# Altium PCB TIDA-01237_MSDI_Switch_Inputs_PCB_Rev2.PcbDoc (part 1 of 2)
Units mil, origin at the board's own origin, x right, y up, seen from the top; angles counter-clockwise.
Board outline 3000 x 5250 mil, 2 copper layers (Top Layer, Bottom Layer), stack 62 mil thick; 161 components, 119 nets, 511 pads, 360 vias.
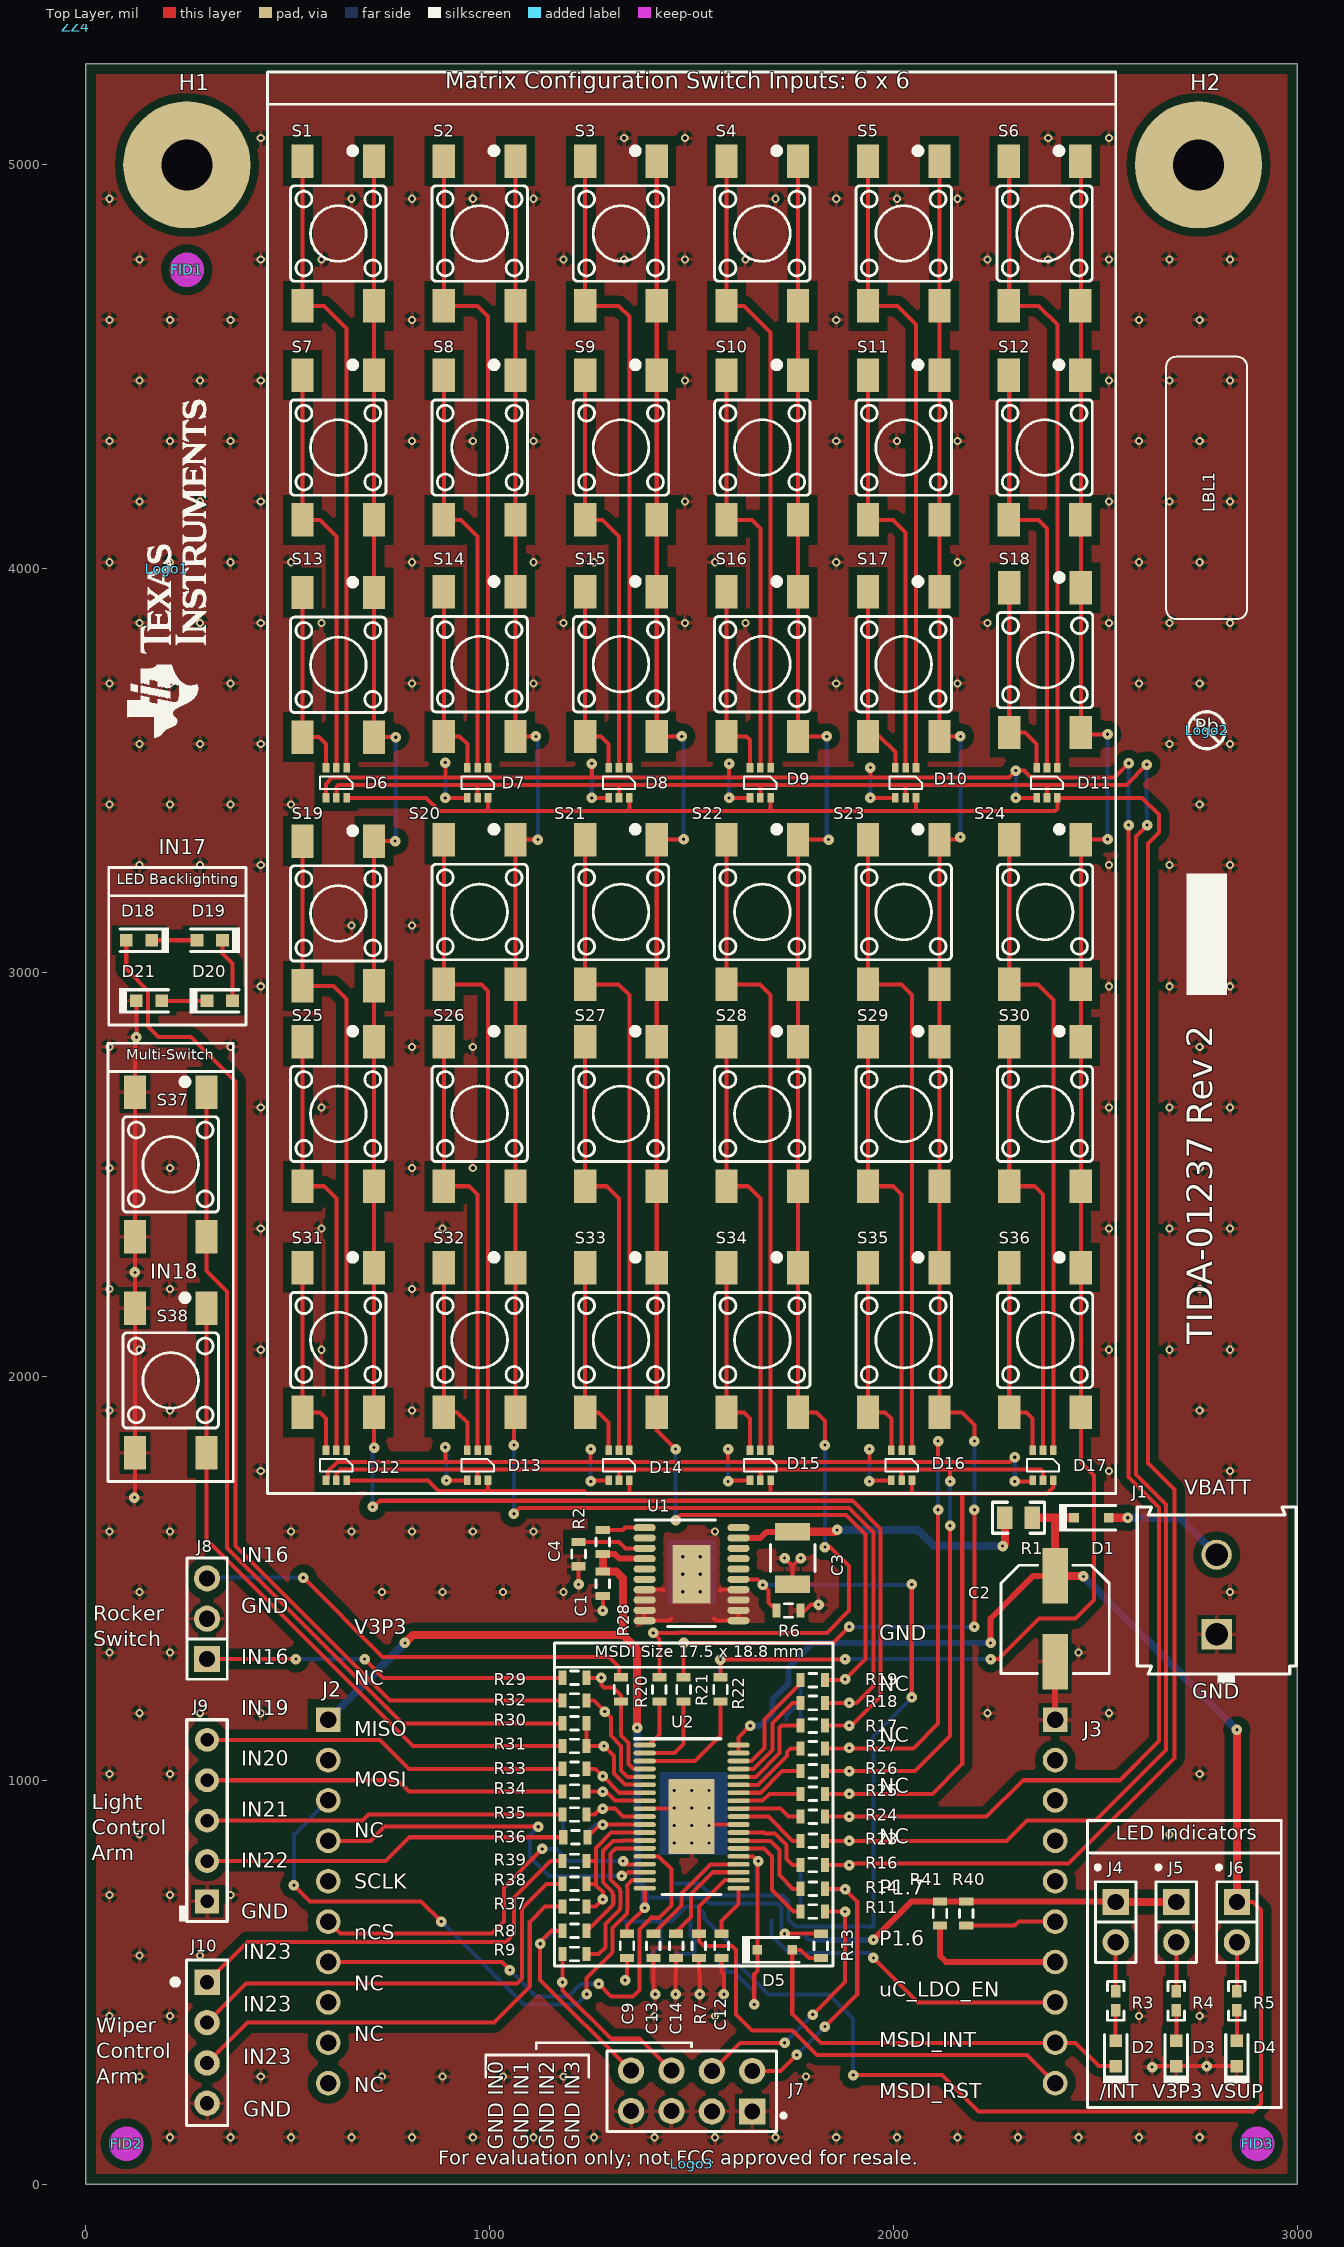
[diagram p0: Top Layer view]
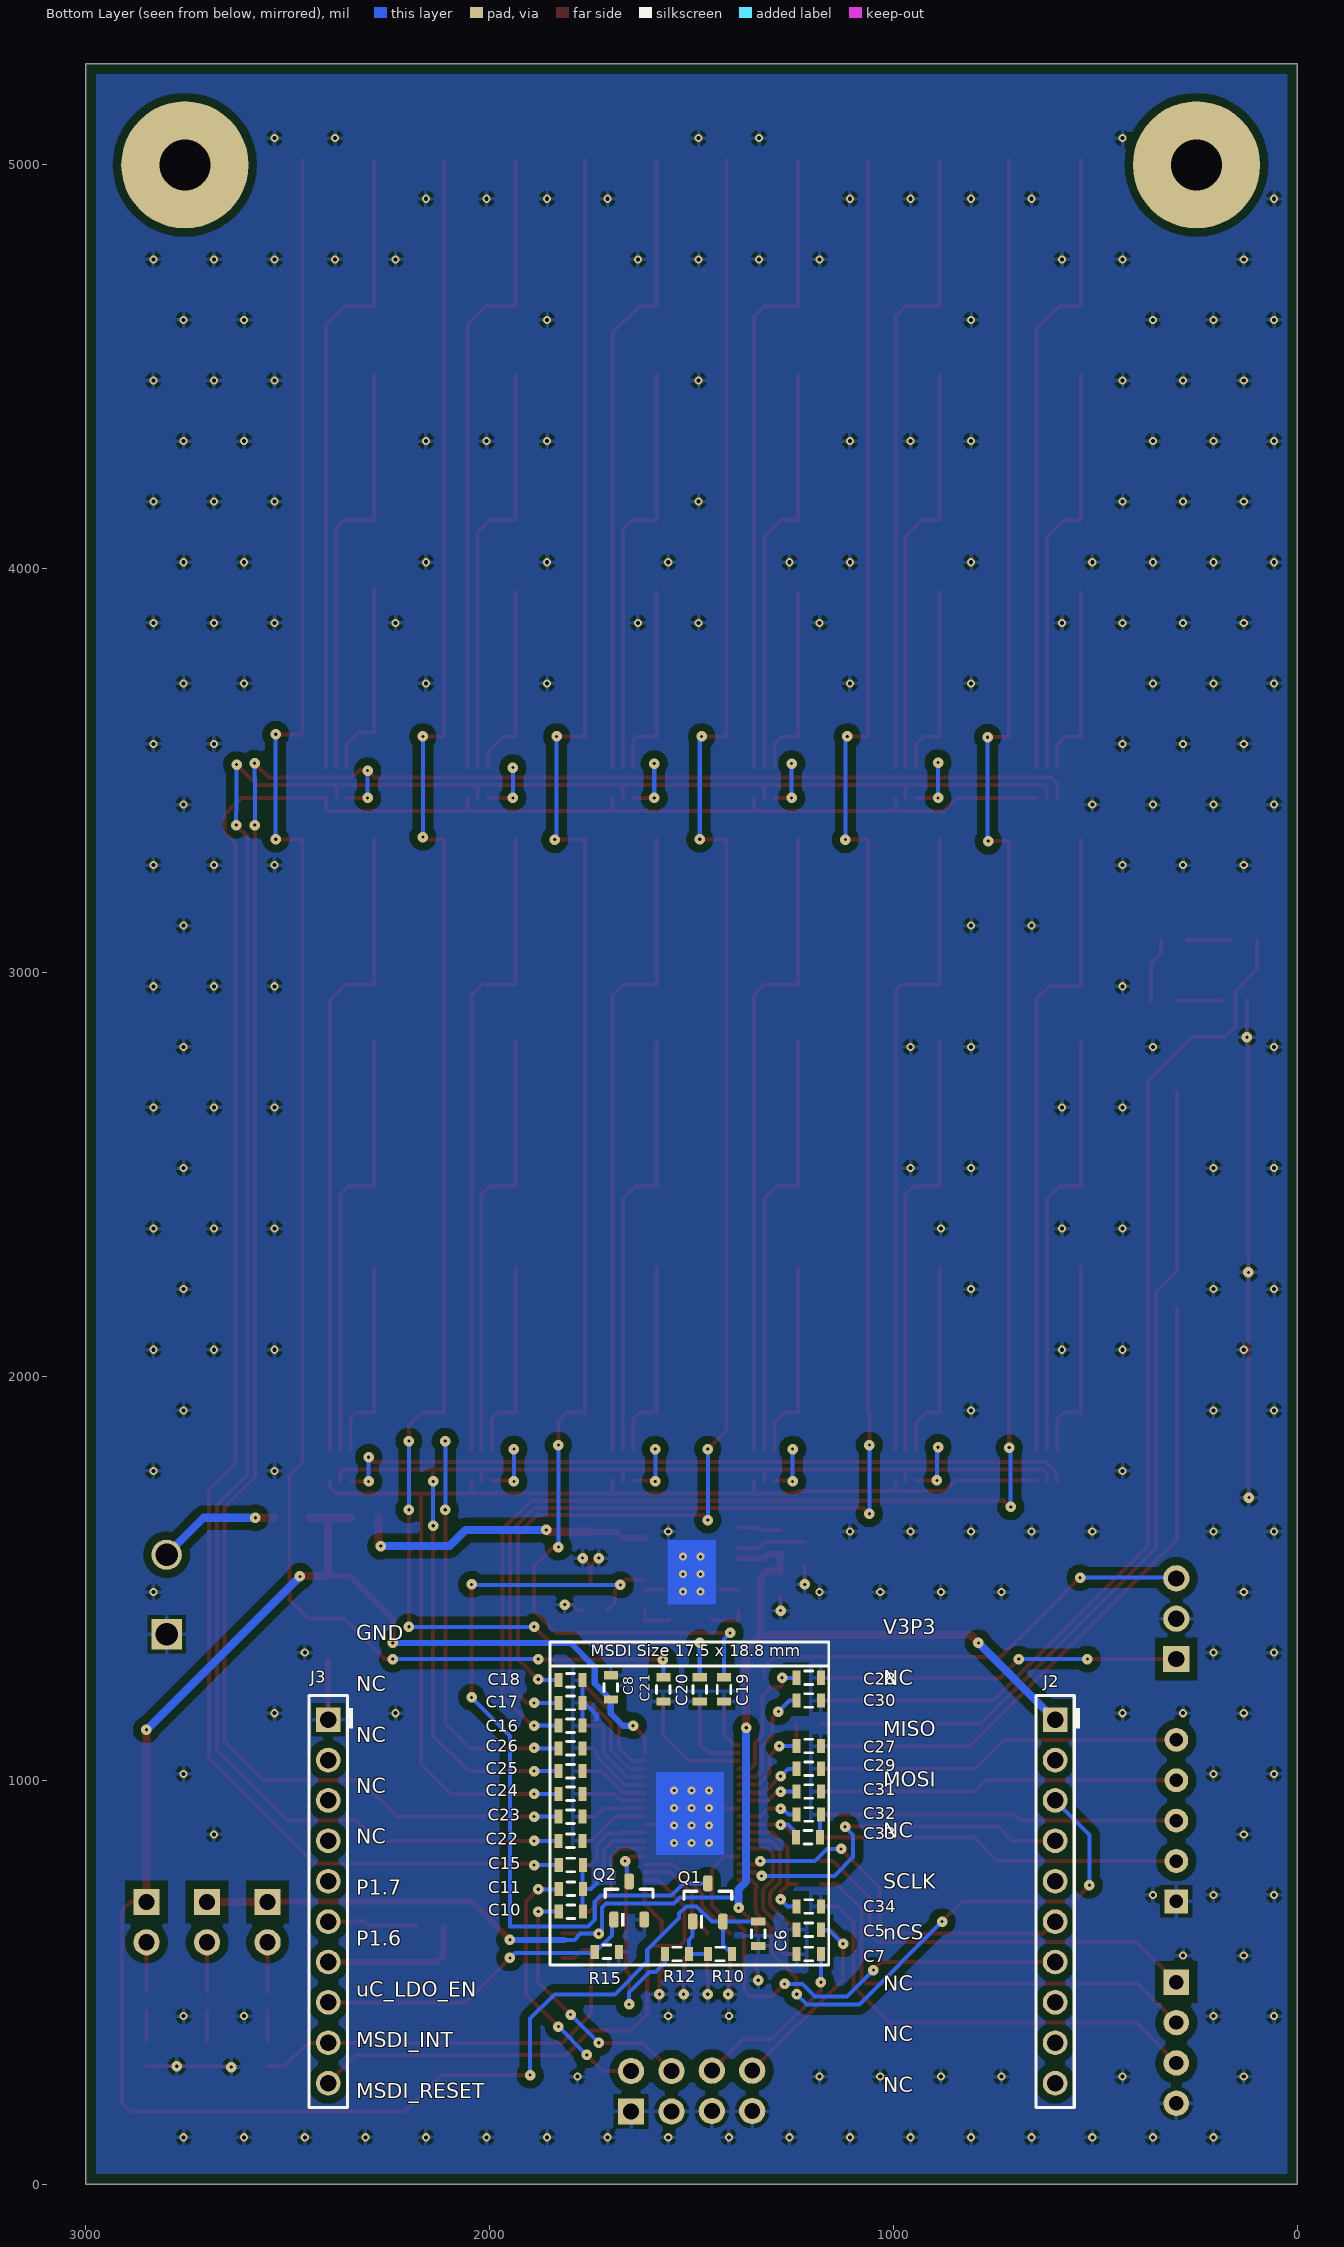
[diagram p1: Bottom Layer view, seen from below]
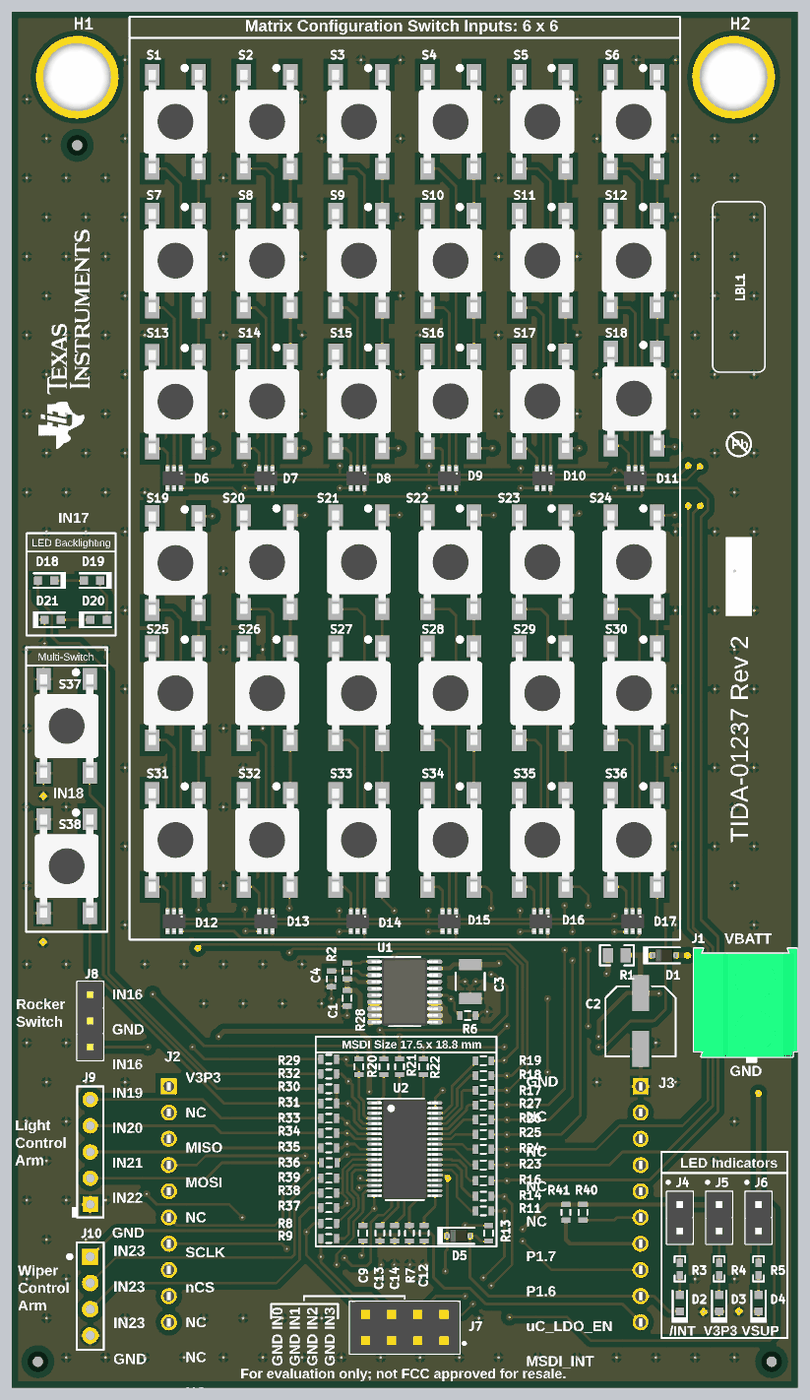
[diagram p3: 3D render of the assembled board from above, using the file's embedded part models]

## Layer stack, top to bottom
Top Solder: solder mask 0.4, Solder Resist, Dk 3.5
Top Layer: signal copper 1.4
Dielectric1: core 59.2, FR-4, Dk 4.8
Bottom Layer: signal copper 1.4
Bottom Solder: solder mask 0.4, Solder Resist, Dk 3.5

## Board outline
0,0 0,5250 3000,5250 3000,0

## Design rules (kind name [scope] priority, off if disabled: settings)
AcuteAngle [All] p1: minimum=4.50000000000000E+0001 checktracksonly=FALSE
AssemblyTestPointUsage [All] p1: valid=2
BoardOutlineClearance BoardOutlineClearance_MountingHoles [OnCopper and InComponentClass('Mounting Holes')] p1: gap=40
BoardOutlineClearance BoardOutlineClearance_Poly [OnCopper and IsPoly] p2: gap=25
BoardOutlineClearance [OnCopper and Not InComponentClass('Logo') and not InComponentClass('FiducialMark') and not InRegion(1000,500,4000,800) and not InPoly] p3: gap=75 except(45: Via-OutlineEdge)
Clearance Clearance_Keepouts [((IsTrack Or IsArc) And Not InPoly) And IsFree and IsKeepOut vs ((IsTrack Or IsArc) And Not InPoly) And IsFree and IsKeepOut] p1: gap=0
Clearance Clearance_Poly [InPolygon] p2: gap=20
Clearance [All] p3: gap=7.87
ComponentClearance ComponentClearance_MountingHoles_FiducialMarks [InComponentClass('Mounting Holes') vs InComponentClass('FiducialMark')] p1: gap=10 collisioncheckmode=3 verticalgap=10 showdistances=FALSE
ComponentClearance ComponentClearance_Shunt [InComponentClass('Header') vs InComponentClass('Shunt')] p2: gap=0 collisioncheckmode=3 verticalgap=0 showdistances=FALSE
ComponentClearance ComponentClearance_Logo [InComponentClass('Logo')] p3: gap=50 collisioncheckmode=3 verticalgap=10 showdistances=FALSE
ComponentClearance ComponentClearance_ScrewToNut [(HasFootprint('NY PMS 440 0025 PH')) vs (HasFootprint('Keystone_1902C'))] p4: gap=5 collisioncheckmode=3 verticalgap=10 showdistances=FALSE
ComponentClearance ComponentClearance_MountingHoles [InComponentClass('Mounting Holes')] p5: gap=100 collisioncheckmode=3 verticalgap=100000 showdistances=FALSE
ComponentClearance ComponentClearance_SmallPassives [HasFootprint('0201*') or HasFootprint('0402*') or HasFootprint('0508') or HasFootprint('0603*') or HasFootprint('0612') or HasFootprint('0805*') or HasFootprint('0815*') or HasFootprint('0830*') or HasFootprint('1206*') or HasFootprint('1210*') or HasFootprint('1808*') or HasFootprint('1812*') or HasFootprint('1825*') or HasFootprint('2010*') or HasFootprint('2220*') or HasFootprint('2225*') or HasFootprint('2512*') or HasFootprint('2728*') or HasFootprint('3518*') vs HasFootprint('0201*') or HasFootprint('0402*') or HasFootprint('0508') or HasFootprint('0603*') or HasFootprint('0612') or HasFootprint('0805*') or HasFootprint('0815*') or HasFootprint('0830*') or HasFootprint('1206*') or HasFootprint('1210*') or HasFootprint('1808*') or HasFootprint('1812*') or HasFootprint('1825*') or HasFootprint('2010*') or HasFootprint('2220*') or HasFootprint('2225*') or HasFootprint('2512*') or HasFootprint('2728*') or HasFootprint('3518*')] p6: gap=14.96 collisioncheckmode=3 verticalgap=10 showdistances=FALSE
ComponentClearance ComponentClearance_THtoSMT [IsThruComponent vs IsSMTComponent] p7: gap=40 collisioncheckmode=3 verticalgap=30 showdistances=FALSE
ComponentClearance ComponentClearance_THtoTH [IsThruComponent vs IsThruComponent] p8: gap=30 collisioncheckmode=3 verticalgap=30 showdistances=FALSE
ComponentClearance [All] p9: gap=30 collisioncheckmode=3 verticalgap=10 showdistances=FALSE
DiffPairsRouting [All] p1: maxlimit=100 minlimit=10 mostfreqgap=10 toplayer_minwidth=15 toplayer_maxwidth=15 toplayer_prefwidth=15 bottomlayer_minwidth=15 bottomlayer_maxwidth=15 bottomlayer_prefwidth=15 maxuncoupledlength=1000
FabricationTestPointUsage TestPointUsage [All] p1: valid=2 allowmultiple=FALSE
FabricationTestpoint Testpoint [All] p1: side=3 testpointundercomponent=TRUE minsize=40 maxsize=100 preferedsize=60 minholesize=0 maxholesize=40 preferedholesize=32 testpointgrid=1 allowsidetop=TRUE allowsidebottom=TRUE usegrid=TRUE gridtolerance=0.01
FanoutControl Fanout_LCC [IsLCC] p1: bgadir=Out bgaviamode=Centered fanoutstyle=Auto fanoutdirection=Alternating viagrid=1 // Fanout_LCC (Default Rule)
FanoutControl Fanout_BGA [IsBGA] p2: bgadir=Out bgaviamode=Centered fanoutstyle=Auto fanoutdirection=Alternating viagrid=1 // Fanout_BGA (Default Rule)
FanoutControl Fanout_Default [All] p4: bgadir=Out bgaviamode=Centered fanoutstyle=Auto fanoutdirection=Alternating viagrid=1 // Fanout_Default (Default Rule)
FanoutControl Fanout_Small [(CompPinCount < 5)] p5: bgadir=Out bgaviamode=Centered fanoutstyle=Auto fanoutdirection=OutThenIn viagrid=1 // Fanout_Small (Default Rule)
HoleSize [All] p1: absolutevalues=TRUE maxlimit=251 minlimit=7.87 maxpercent=80.000 minpercent=20.000
MinimumAnnularRing MinimumAnnularRing_ThermalPadVias [IsVia and InAnyComponent] p1: minimumring=5.91
MinimumAnnularRing [All] p2: minimumring=5
MinimumSolderMaskSliver MinimumSolderMaskSliver_Logo [InComponentClass('Logo') vs InComponentClass('Logo')] p1: minsoldermaskwidth=0.7
MinimumSolderMaskSliver [All] p2: minsoldermaskwidth=3.94
PlaneClearance [All] p1: clearance=15
PlaneConnect [All] p1: planeconnectstyle=Relief reliefexpansion=10 reliefentries=4 reliefconductorwidth=10 reliefairgap=10
PolygonConnect PolygonConnect_LDO [HasFootprint('PWP0020D_N')] p1: connectstyle=Direct reliefconductorwidth=10 reliefentries=4 polygonreliefangle="90 Angle" airgapwidth=10
PolygonConnect [All] p2: connectstyle=Relief reliefconductorwidth=10 reliefentries=4 polygonreliefangle="90 Angle" airgapwidth=10
RoutingVias ThermalPadVias [IsVia and InAnyComponent] p1: holewidth=7.87 width=19.68 viastyle="Through Hole" minholewidth=7.87 minwidth=19.68 maxholewidth=12.99 maxwidth=23.62
RoutingVias [All] p2: holewidth=7.87 width=26 viastyle="Through Hole" minholewidth=7.87 minwidth=20 maxholewidth=40 maxwidth=65
SilkToBoardRegionClearance [Not ((IsComment or IsDesignator) And (Hide <> 'False')) and not InRegion(1000,500,4000,800)] p1:
SilkToSilkClearance SilkToSilkClearance_Pb-FreeLogo [(HasFootprint('Pb-Free_Overlay_Medium') OR HasFootprint('Pb-Free_Overlay_Small')) vs (HasFootprint('Pb-Free_Overlay_Medium') OR HasFootprint('Pb-Free_Overlay_Small'))] p1: silktosilkclearance=0
SilkToSilkClearance [All] p2: silktosilkclearance=4
SilkToSolderMaskClearance SilkToComponentPadClearance [IsPad and InAnycomponent] p1: minsilkscreentomaskgap=5 clearancetoexposedcopper=TRUE
SilkToSolderMaskClearance "Silk to Solder Mask Opening" [All] p2: minsilkscreentomaskgap=4 clearancetoexposedcopper=FALSE
SolderMaskExpansion [All] p1: expansion=1.97
Width [All] p1: maxlimit=100 minlimit=6 preferedwidth=10 checkconnectedcopper=TRUE
14 further rules are at their usual default settings.

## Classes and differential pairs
component class "Mounting Holes": H1 H2
component class TIDA-01237_MSDI_Matrix_Inputs: C15 C16 C17 C18 C19 C20 C21 C22 C23 C24 C25 C26 D6 D7 D8 D9 D10 D11 D12 D13 D14 D15 D16 D17 R16 R17 R18 R19 R20 R21 R22 R23 R24 R25 R26 R27 S1 S2 S3 S4 S5 S6 S7 S8 S9 S10 S11 S12 S13 S14 S15 S16 S17 S18 S19 S20 S21 S22 S23 S24 S25 S26 S27 S28 S29 S30 S31 S32 S33 S34 S35 S36
component class Header: J4 J5 J6 J8 J9
component class Logo: Logo1
component class TIDA-01237_MSDI_Hardware: FID1 FID2 FID3 H1 H2 LBL1 Logo1 Logo2 Logo3 ZZ1 ZZ2 ZZ3 ZZ4
component class FiducialMark: FID1 FID2 FID3
component class AssemblyNote: ZZ1 ZZ2 ZZ3 ZZ4
component class Label: LBL1
component class TIDA-01237_MSDI_Main: C1 C2 C3 C4 C5 C6 C7 C8 C9 C10 C11 C12 C13 C14 D1 D2 D3 D4 D5 J1 J2 J3 J4 J5 J6 J7 Q1 Q2 R1 R2 R3 R4 R5 R6 R7 R8 R9 R10 R11 R12 R13 R14 R15 R40 R41 U1 U2
component class TIDA-01237_MSDI_Resistor_Coded_Inputs: C27 C28 C29 C30 C31 C32 C33 C34 D18 D19 D20 D21 J8 J9 J10 R28 R29 R30 R31 R32 R33 R34 R35 R36 R37 R38 R39 S37 S38

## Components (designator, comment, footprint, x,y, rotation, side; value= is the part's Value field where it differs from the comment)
C1 "C1608X5R1A106M080AC" 0603S 1280,1486.45 r270 top
C2 "EMVE500ADA470MF80G" CAPSMT_62_F80 2400,1400 r270 top
C3 "C3225X7R1H106M250AC" 1210_280 1750,1550.31 r270 top
C4 "C0603C103J5RACTU" 0603S 1220,1560 r270 top
C5 "C0603C153J3GACTU" 0603S 1210,629.69 r0 bottom
C6 "0603YC104JAT2A" 0603S 1335,620 r270 bottom
C7 "C0603C153J3GACTU" 0603S 1210,569.69 r0 bottom
C8 "06035C104KAT2A" 0603S 1700,1230 r90 bottom
C9 "0603YC104JAT2A" 0603S 1340,590 r270 top
C10 "C0603C153J3GACTU" 0603S 1799.18,674.68 r180 bottom
C11 "C0603C153J3GACTU" 0603S 1799.18,730.99 r180 bottom
C12 "C1608X7R1E104K080AA" 0603S 1574.1,590 r270 top
C13 "C1608X7R1E104K080AA" 0603S 1405.18,590 r270 top
C14 "C1608X7R1C105K080AC" 0603S 1461.48,590 r270 top
C15 "C0603C153J3GACTU" 0603S 1799.18,790 r180 bottom
C16 "C0603C153J3GACTU" 0603S 1800,1135.24 r180 bottom
C17 "C0603C153J3GACTU" 0603S 1800,1191.54 r180 bottom
C18 "C0603C153J3GACTU" 0603S 1800,1247.85 r180 bottom
C19 "C0603C153J3GACTU" 0603S 1420,1225 r270 bottom
C20 "C0603C153J3GACTU" 0603S 1480,1225 r270 bottom
C21 "C0603C153J3GACTU" 0603S 1570,1225 r270 bottom
C22 "C0603C153J3GACTU" 0603S 1800,850 r180 bottom
C23 "C0603C153J3GACTU" 0603S 1800,910 r180 bottom
C24 "C0603C153J3GACTU" 0603S 1800,966.31 r180 bottom
C25 "C0603C153J3GACTU" 0603S 1800,1022.62 r180 bottom
C26 "C0603C153J3GACTU" 0603S 1800,1078.93 r180 bottom
C27 "C0603C153J3GACTU" 0603S 1210,1084.76 r180 bottom
C28 "C0603C153J3GACTU" 0603S 1210,1253.69 r180 bottom
C29 "C0603C153J3GACTU" 0603S 1210,1028.45 r180 bottom
C30 "C0603C153J3GACTU" 0603S 1210,1197.38 r180 bottom
C31 "C0603C153J3GACTU" 0603S 1210,972.15 r180 bottom
C32 "C0603C153J3GACTU" 0603S 1210,915.24 r180 bottom
C33 "C0603C153J3GACTU" 0603S 1211.95,858.93 r180 bottom
C34 "C0603C153J3GACTU" 0603S 1210,687.38 r180 bottom
D1 "B0540WS-7" SOD-323 2490,1650 r0 top
D2 "150060VS75000" WL-SMCW_GREEN 2550,323.47 r90 top
D3 "150060VS75000" WL-SMCW_GREEN 2700,323.47 r90 top
D4 "150060VS75000" WL-SMCW_GREEN 2850,323.47 r90 top
D5 "SDMK0340L-7-F" SOD-323 1705.78,580 r0 top
D6 "BAS40TW-7-F" SOT-363 620,3470 r270 top
D7 "BAS40TW-7-F" SOT-363 970,3470 r270 top
D8 "BAS40TW-7-F" SOT-363 1320,3470 r270 top
D9 "BAS40TW-7-F" SOT-363 1670,3470 r270 top
D10 "BAS40TW-7-F" SOT-363 2030,3470 r270 top
D11 "BAS40TW-7-F" SOT-363 2380,3470 r270 top
D12 "BAS40TW-7-F" SOT-363 620,1780 r270 top
D13 "BAS40TW-7-F" SOT-363 970,1780 r270 top
D14 "BAS40TW-7-F" SOT-363 1320,1780 r270 top
D15 "BAS40TW-7-F" SOT-363 1670,1780 r270 top
D16 "BAS40TW-7-F" SOT-363 2020,1780 r270 top
D17 "BAS40TW-7-F" SOT-363 2370,1780 r270 top
D18 "150060VS75000" WL-SMCW_GREEN 131.54,3080 r180 top
D19 "150060VS75000" WL-SMCW_GREEN 306.54,3080 r180 top
D20 "150060VS75000" WL-SMCW_GREEN 331.54,2930 r0 top
D21 "150060VS75000" WL-SMCW_GREEN 156.54,2930 r0 top
FID1 "Fiducial" Fiducial10-20 250,4740 r0 top
FID2 "Fiducial" Fiducial10-20 100,100 r0 top
FID3 "Fiducial" Fiducial10-20 2900,100 r0 top
H1 "NY PMS 440 0025 PH" "NY PMS 440 0025 PH" 250,5000 r0 top
H2 "NY PMS 440 0025 PH" "NY PMS 440 0025 PH" 2755,5000 r0 top
J1 "282856-2" TE_282856-2 2800,1460 r90 top
J2 "SSW-110-01-T-S" Samtec_SSW-110-x1-x-S 600,700 r270 bottom
J3 "SSW-110-01-T-S" Samtec_SSW-110-x1-x-S 2400,700 r270 bottom
J4 "90120-0122" CONN_90120-0122 2550,648.81 r270 top
J5 "90120-0122" CONN_90120-0122 2700,648.81 r270 top
J6 "90120-0122" CONN_90120-0122 2850,648.81 r270 top
J7 "PPPC042LFBN-RC" CONN_PPPC042LFBN-RC 1650,180 r0 top
J8 "PBC03SAAN" PBC03SAAN 300,1400 r90 top
J9 "800-10-005-10-001000" Mill-Max_800-10-005-10-001000 300,900 r90 top
J10 "76308-204LF" FCI_76308-204LF 300,350 r90 top
LBL1 "Size: 0.65\" x 0.20 \"" Label_650x200 2775,4200 r90 top
Logo1 "Texas Instruments" TI_Stacked_Overlay_Small 200,4000 r90 top
Logo2 "Pb-Free Symbol" Pb-Free_Overlay_Small 2775,3600 r0 top
Logo3 "FCC disclaimer" FCC_disclaimer 1500,50 r0 top
Q1 "BC857C-7-F" SOT-23 1460,697.45 r90 bottom
Q2 "2N7002" SOT-23 1655,702.45 r90 bottom
R1 "5106" 5106 2310,1650 r180 top
R2 "CRCW060310K0JNEA" 0603S 1280,1590 r270 top
R3 "ERJ-2RKF49R9X" 0402 2550,453.8 r90 top
R4 "CRCW040268R0JNED" 0402 2700,453.8 r90 top
R5 "CRCW0402604RFKED" 0402 2850,453.8 r90 top
R6 "CRCW060310K0JNEA" 0603S 1740,1420.31 r180 top
R7 "CRCW060310K0JNEA" 0603S 1517.79,590 r90 top
R8 "CRCW0603100RFKEA" 0603S 1210,627.38 r0 top
R9 "CRCW0603100RFKEA" 0603S 1210,569.69 r0 top
R10 "CRCW060310K0JNEA" 0603S 1430,570 r180 bottom
R11 "CRCW0603100RFKEA" 0603S 1800,674.99 r180 top
R12 "CRCW060310K0JNEA" 0603S 1536.45,570 r0 bottom
R13 "CRCW060310K0JNEA" 0603S 1820,590 r90 top
R14 "CRCW0603100RFKEA" 0603S 1800,731.3 r180 top
R15 "CRCW060310K0JNEA" 0603S 1710,575 r180 bottom
R16 "CRCW0603100RFKEA" 0603S 1800,790 r180 top
R17 "CRCW0603100RFKEA" 0603S 1800,1135.24 r180 top
R18 "CRCW0603100RFKEA" 0603S 1800,1191.54 r180 top
R19 "CRCW0603100RFKEA" 0603S 1800,1247.85 r180 top
R20 "CRCW0603100RFKEA" 0603S 1420,1225 r270 top
R21 "CRCW0603100RFKEA" 0603S 1480,1225 r270 top
R22 "CRCW0603100RFKEA" 0603S 1571.23,1225 r270 top
R23 "CRCW0603100RFKEA" 0603S 1800,850 r180 top
R24 "CRCW0603100RFKEA" 0603S 1800,910 r180 top
R25 "CRCW0603100RFKEA" 0603S 1800,966.31 r180 top
R26 "CRCW0603100RFKEA" 0603S 1800,1022.62 r180 top
R27 "CRCW0603100RFKEA" 0603S 1800,1078.93 r180 top
R28 "CRCW0603909RFKEA" 0603S 1325,1225 r270 top
R29 "CRCW0603604RFKEA" 0603S 1210,1253.69 r0 top
R30 "CRCW0603392RFKEA" 0603S 1210,1141.07 r0 top
R31 "CRCW0603511RFKEA" 0603S 1210,1084.76 r0 top
R32 "CRCW060349R9FKEA" 0603S 1210,1197.38 r0 top
R33 "CRCW0603909RFKEA" 0603S 1210,1028.46 r0 top
R34 "CRCW0603604RFKEA" 0603S 1210,972.15 r0 top
R35 "CRCW0603309RFKEA" 0603S 1210,915.24 r0 top
R36 "CRCW06031K21FKEA" 0603S 1211.95,858.93 r0 top
R37 "CRCW06035K36FKEA" 0603S 1210,687.38 r0 top
R38 "CRCW06034K64FKEA" 0603S 1210,743.69 r0 top
R39 "CRCW06031K96FKEA" 0603S 1210,800 r0 top
R40 "RC0603JR-0710KL" 0603S 2180,670 r90 top
R41 "RC0603JR-0710KL" 0603S 2115,670 r90 top
S1 "4-1437565-1" SW_FSM4JSMA 625,4830 r0 top
S2 "4-1437565-1" SW_FSM4JSMA 975,4830 r0 top
S3 "4-1437565-1" SW_FSM4JSMA 1325,4830 r0 top
S4 "4-1437565-1" SW_FSM4JSMA 1675,4830 r0 top
S5 "4-1437565-1" SW_FSM4JSMA 2025,4830 r0 top
S6 "4-1437565-1" SW_FSM4JSMA 2373.93,4830 r0 top locked
S7 "4-1437565-1" SW_FSM4JSMA 625,4300 r0 top
S8 "4-1437565-1" SW_FSM4JSMA 975,4300 r0 top
S9 "4-1437565-1" SW_FSM4JSMA 1325,4300 r0 top
S10 "4-1437565-1" SW_FSM4JSMA 1675,4300 r0 top
S11 "4-1437565-1" SW_FSM4JSMA 2025,4300 r0 top
S12 "4-1437565-1" SW_FSM4JSMA 2373.93,4300 r0 top
S13 "4-1437565-1" SW_FSM4JSMA 625,3761.89 r0 top
S14 "4-1437565-1" SW_FSM4JSMA 975,3763.66 r0 top
S15 "4-1437565-1" SW_FSM4JSMA 1325,3763.66 r0 top
S16 "4-1437565-1" SW_FSM4JSMA 1675,3763.66 r0 top
S17 "4-1437565-1" SW_FSM4JSMA 2025,3763.66 r0 top
S18 "4-1437565-1" SW_FSM4JSMA 2375,3773.66 r0 top
S19 "4-1437565-1" SW_FSM4JSMA 625,3146.34 r0 top
S20 "4-1437565-1" SW_FSM4JSMA 975,3150 r0 top
S21 "4-1437565-1" SW_FSM4JSMA 1325,3150 r0 top
S22 "4-1437565-1" SW_FSM4JSMA 1675,3150 r0 top
S23 "4-1437565-1" SW_FSM4JSMA 2025,3150 r0 top
S24 "4-1437565-1" SW_FSM4JSMA 2375,3150 r0 top
S25 "4-1437565-1" SW_FSM4JSMA 625,2650 r0 top
S26 "4-1437565-1" SW_FSM4JSMA 975,2650 r0 top
S27 "4-1437565-1" SW_FSM4JSMA 1325,2650 r0 top
S28 "4-1437565-1" SW_FSM4JSMA 1675,2650 r0 top
S29 "4-1437565-1" SW_FSM4JSMA 2025,2650 r0 top
S30 "4-1437565-1" SW_FSM4JSMA 2375,2650 r0 top
S31 "4-1437565-1" SW_FSM4JSMA 625,2090 r0 top
S32 "4-1437565-1" SW_FSM4JSMA 975,2090 r0 top
S33 "4-1437565-1" SW_FSM4JSMA 1325,2090 r0 top
S34 "4-1437565-1" SW_FSM4JSMA 1675,2090 r0 top
S35 "4-1437565-1" SW_FSM4JSMA 2025,2090 r0 top
S36 "4-1437565-1" SW_FSM4JSMA 2375,2090 r0 top
S37 "4-1437565-1" SW_FSM4JSMA 210,2524.89 r0 top
S38 "4-1437565-1" SW_FSM4JSMA 210,1990 r0 top
U1 "TPS7B6733QPWPRQ1" PWP0020D_N 1499.68,1510.31 r0 top
U2 "TIC12400DCPQ1" DCP0038A_N 1500,910 r0 top
ZZ1 "This Assembly Note is for PCB labels only" AssemblyNoteLabel -25,5628 r0 top
ZZ2 "These assemblies are ESD sensitive, ESD precautions shall be observed." AssemblyNote -25,5519.11 r0 top
ZZ3 "These assemblies must be clean and free from flux and all contaminants. Use of no clean flux is not acceptable." AssemblyNote -25,5430.56 r0 top
ZZ4 "These assemblies must comply with workmanship standards IPC-A-610 Class 2, unless otherwise specified." AssemblyNote -25,5342 r0 top

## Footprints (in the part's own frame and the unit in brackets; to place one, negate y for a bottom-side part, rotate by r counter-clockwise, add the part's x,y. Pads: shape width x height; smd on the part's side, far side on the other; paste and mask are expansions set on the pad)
0402 [mm] "0402 from SM-752 data"
  rect 0.8x0.6 smd: 1(-0.6,0) 2(0.6,0)
  silkscreen extent -1.22,-0.52 1.22,0.52, body extent -0.55,-0.3 0.55,0.3, height 0.6
0603S [mil]
  rect 20x35 smd: 1(-30,0) 2(30,0)
  silkscreen extent -10,-17 10,17, body extent -34,-19 34,19, height 39
1210_280 [mm] "SMD, 2-Leads, Body 3.6x2.8mm, Height 2.8mm"
  rect 1.1x2.2 smd: 1(-1.65,0) 2(1.65,0)
  silkscreen extent -0.84,-1.4 0.84,1.4, body extent -1.8,-1.4 1.8,1.4, height 2.8
5106 [mm] "Keystone"
  rect 0.99x1.4 smd: 1(-0.85,0) 2(0.88,0)
  silkscreen extent -1.63,-0.97 1.65,0.97, body extent -1.06,-0.69 1.06,0.69, height 0.84
AssemblyNote [mil] "Assembly Note"
AssemblyNoteLabel [mil] "Assembly Note for PCB Labels"
CAPSMT_62_F80 [mm] "6.3 x 7.7mm:  Chemi-Con F80"
  rect 3.5x1.6 smd: 1(-2.7,0) 2(2.7,0)
  silkscreen extent -3.36,-3.4 3.44,3.4, body extent -3.4,-3.4 3.44,3.4, height 8
CONN_90120-0122 [mm] "Molex"
  rect 1.65x1.65 hole 1.016 mask+0: 1(-1.27,0)
  round 1.65 hole 1.016 mask+0: 2(1.27,0)
  silkscreen extent -3.56,-1.27 2.54,1.27, body extent -2.54,-1.27 2.54,1.27, height 9.29
CONN_PPPC042LFBN-RC [mm] "Sullins socket, 100 mil spacing, 4x2"
  rect 1.65x1.65 hole 1 mask+0: 1(0,0)
  round 1.65 hole 1 mask+0: 2(0,2.54) 3(-2.54,0) 4(-2.54,2.54) 5(-5.08,0.025) 6(-5.08,2.565) 7(-7.62,0.025) 8(-7.62,2.565)
  silkscreen extent -9.14,-1.27 2.09,3.81, body extent -9.14,-1.27 1.52,3.81, height 8.52
DCP0038A_N [mm] "SOP, 38-Leads, Body 9.8x4.5mm, Pitch 0.5mm, Thermal Pad 4.7x2.9mm, IPC Medium Density"
  oval 1.4x0.3 smd: 1(-2.95,4.5) 2(-2.95,4) 3(-2.95,3.5) 4(-2.95,3) 5(-2.95,2.5) 6(-2.95,2) 7(-2.95,1.5) 8(-2.95,1) 9(-2.95,0.5) 10(-2.95,0) 11(-2.95,-0.5) 12(-2.95,-1) 13(-2.95,-1.5) 14(-2.95,-2) 15(-2.95,-2.5) 16(-2.95,-3) 17(-2.95,-3.5) 18(-2.95,-4) 19(-2.95,-4.5) 20(2.95,-4.5) 21(2.95,-4) 22(2.95,-3.5) 23(2.95,-3) 24(2.95,-2.5) 25(2.95,-2) 26(2.95,-1.5) 27(2.95,-1) 28(2.95,-0.5) 29(2.95,0) 30(2.95,0.5) 31(2.95,1) 32(2.95,1.5) 33(2.95,2) 34(2.95,2.5) 35(2.95,3) 36(2.95,3.5) 37(2.95,4) 38(2.95,4.5)
  rrect3% 2.9x4.7 smd: 39(0,0)
  silkscreen extent -3.6,-4.9 1.85,4.9, body extent -3.21,-4.85 3.21,4.85, height 1.2
FCC_disclaimer [mil]
FCI_76308-204LF [mm] "FCI"
  rect 1.6x1.6 hole 0.9: 1(3.81,0)
  round 1.6 hole 0.9: 2(1.27,0) 3(-1.27,0) 4(-3.81,0)
  silkscreen extent -5.2,-1.3 5.2,2.18, body extent -5.19,-1.27 5.19,1.27, height 8.52
Fiducial10-20 [mm]
  round 1 smd mask+0.5: 1(0,0)
  Top Layer keep-out circle w1.178: c0,0 r0.5
Label_650x200 [mil] "Thermal Transfer Label"
  silkscreen extent -325,-100 325,100, body extent -325,-100 325,100, height 1
Mill-Max_800-10-005-10-001000 [mm] "Mill-Max"
  rect 1.5x1.5 hole 0.85: 1(-5.08,0)
  round 1.5 hole 0.85: 2(-2.54,0) 3(0,0) 4(2.54,0) 5(5.08,0)
  silkscreen extent -6.35,-1.27 6.35,1.78, body extent -6.35,-1.27 6.35,1.27, height 8.13
"NY PMS 440 0025 PH" [mm] "4-40 nylon screw and mounting hole"
  round 8 hole 3.2: 1(0,0)
  body extent -3.3,-3.3 3.3,3.3, height 2.69
Pb-Free_Overlay_Small [mil]
  silkscreen extent -46,-46 46,46
PBC03SAAN [mm] "Sullins 100mil, 1x3, 230 mil above insulator"
  rect 1.65x1.65 hole 1.016: 1(-2.54,0)
  round 1.65 hole 1.016: 2(0,0) 3(2.54,0)
  silkscreen extent -3.81,-1.27 3.81,1.27, body extent -3.81,-1.27 3.81,1.27, height 8.38
PWP0020D_N [mm] "SOP, 20-Leads, Body 6.4x4.4mm, Pitch 0.65mm, Thermal Pad 2x3mm, IPC Medium Density"
  rrect100% 1.4x0.45 smd: 1(-2.95,2.925) 2(-2.95,2.275) 3(-2.95,1.625) 4(-2.95,0.975) 5(-2.95,0.325) 6(-2.95,-0.325) 7(-2.95,-0.975) 8(-2.95,-1.625) 9(-2.95,-2.275) 10(-2.95,-2.925) 11(2.95,-2.925) 12(2.95,-2.275) 13(2.95,-1.625) 14(2.95,-0.975) 15(2.95,-0.325) 16(2.95,0.325) 17(2.95,0.975) 18(2.95,1.625) 19(2.95,2.275) 20(2.95,2.925)
  rrect4% 2.4x3.7 smd: 21(0,0)
  silkscreen extent -3.55,-3.3 1.5,3.4, body extent -3.21,-3.25 3.21,3.25, height 1
Samtec_SSW-110-x1-x-S [mm] "Receptacle, 2.54mm, 10x1, TH"
  rect 1.55x1.55 hole 1.04: 1(-11.43,0)
  round 1.55 hole 1.04: 2(-8.89,0) 3(-6.35,0) 4(-3.81,0) 5(-1.27,0) 6(1.27,0) 7(3.81,0) 8(6.35,0) 9(8.89,0) 10(11.43,0)
  silkscreen extent -12.95,-1.21 12.95,1.55, body extent -12.95,-1.21 12.95,1.21, height 8.51
SOD-323 [mm] "NXP recommended land pattern"
  rect 0.6x0.6 smd paste-0.05: 1(-1.1,0) 2(1.1,0)
  silkscreen extent -2.06,-0.86 1.53,0.86, body extent -1.3,-0.67 1.3,0.68, height 1.1
SOT-23 [mm] "SOT23, 3-Leads, Body 2.9x1.3mm, Pitch 0.95mm, Lead Span 2.5mm, IPC Medium Density"
  rrect50% 1x0.6 smd: 1(-1.2,0.95) 2(-1.2,-0.95) 3(1.2,0)
  silkscreen extent -1.62,-1.5 0.7,1.5, body extent -1.16,-1.45 1.21,1.45, height 1
SOT-363 [mm]
  rect 0.6x0.42 smd mask+0.051: 1(-0.95,0.65) 2(-0.95,0) 3(-0.95,-0.65) 4(0.95,-0.65) 5(0.95,0) 6(0.95,0.65)
  silkscreen extent -0.38,-1.02 0.38,1.02, body extent -1.1,-1.1 1.1,1.1, height 1.12
SW_FSM4JSMA [mm] "Alcoswitch"
  rect 1.4x2.1 smd: 1(2.25,4.55) 2(2.25,-4.55) 3(-2.25,4.55) 4(-2.25,-4.55)
  silkscreen extent -3,-3 3,5.4, body extent -3,-5 3,5, height 5.1
TE_282856-2 [mm] "TH, 2-Leads, Body 10x10mm, Pitch 5mm"
  rect 1.9x1.9 hole 1.4: 1(-2.5,0)
  round 1.9 hole 1.4: 2(2.5,0)
  silkscreen extent -5.61,-5 5.5,5, body extent -5,-5 5.5,5, height 19
TI_Stacked_Overlay_Small [mil]
  silkscreen extent -418,-98 418,98
WL-SMCW_GREEN [mm] "WURTH"
  rect 0.8x0.8 smd: 1(-0.8,0) 2(0.8,0)
  silkscreen extent -1.9,-0.8 1.2,0.8, body extent -0.85,-0.45 0.85,0.45, height 0.8

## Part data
C1: "CAP, CERM, 10 µF, 10 V, +/- 20%, X5R, 0603"
C2: "CAP, AL, 47 µF, 50 V, +/- 20%, SMD"
C3: "CAP, CERM, 10 µF, 50 V, +/- 20%, X7R, 1210"
C4: "CAP, CERM, 0.01 µF, 50 V, +/- 5%, X7R, 0603"
C5 C7 C10 C11 C15 C16 C17 C18 C19 C20 C21 C22 C23 C24 C25 C26 C27 C28 C29 C30 C31 C32 C33 C34: "CAP, CERM, 0.015 µF, 25 V, +/- 5%, C0G/NP0, 0603"
C6 C9: "CAP, CERM, 0.1 µF, 16 V, +/- 5%, X7R, 0603"
C8: "CAP, CERM, 0.1 µF, 50 V, +/- 10%, X7R, 0603"
C12 C13: "CAP, CERM, 0.1 µF, 25 V, +/- 10%, X7R, 0603"
C14: "CAP, CERM, 1 µF, 16 V, +/- 10%, X7R, 0603"
D1: "Diode, Schottky, 40 V, 0.5 A, SOD-323"
D2 D3 D4 D18 D19 D20 D21: "LED, Green, SMD"
D5: "Diode, Schottky, 40 V, 0.03 A, SOD-323"
D6 D7 D8 D9 D10 D11 D12 D13 D14 D15 D16 D17: "Diode, Schottky, 40 V, 0.2 A, AEC-Q101, SOT-363"
FID1 FID2 FID3: "Fiducial mark.  There is nothing to buy or mount."
H1 H2: "Machine Screw, Round, #4-40 x 1/4, Nylon, Philips panhead"
J1: "Therminal Block, 5 mm, 2-pole, Tin, TH"
J2 J3: "Receptacle, 2.54mm, 10x1, Tin, TH"
J4 J5 J6: "Header, 100mil, 2x1, Tin, TH"
J7: "Connector, Receptacle, 100mil, 4x2, Gold plated, TH"
J8: "Header, 100mil, 3x1, Gold, TH"
J9: "Header, 100mil, 5x1, TH"
J10: "Receptacle, 100mil, 4x1, Gold, TH"
LBL1: library part THT-14-423-10, "Thermal Transfer Printable Labels, 0.650\" W x 0.200\" H - 10,000 per roll"
Logo1: library part TI_Logo, "Texas Instrument Corporate Signature"
Logo2: library part Pb-Free
Logo3: library part FCC_disclaimer, "FCC_disclaimer"
Q1: library part "BC857C-7-F, Diodes Inc.", "Transistor, PNP, 45 V, 0.1 A, SOT-23"
Q2: "MOSFET, N-CH, 60 V, 115 A, SOT-23"
R1: "RES, 0, 1%, 0.5 W, 0805"
R2 R6 R7 R10 R12 R13 R15 R40 R41: "RES, 10 k, 5%, 0.1 W, 0603"
R3: "RES, 49.9, 1%, 0.1 W, AEC-Q200 Grade 0, 0402"
R4: "RES, 68, 5%, 0.063 W, 0402"
R5: "RES, 604, 1%, 0.063 W, 0402"
R8 R9 R11 R14 R16 R17 R18 R19 R20 R21 R22 R23 R24 R25 R26 R27: "RES, 100, 1%, 0.1 W, 0603"
R28 R33: "RES, 909, 1%, 0.1 W, 0603"
R29 R34: "RES, 604, 1%, 0.1 W, 0603"
R30: "RES, 392, 1%, 0.1 W, 0603"
R31: "RES, 511, 1%, 0.1 W, 0603"
R32: "RES, 49.9, 1%, 0.1 W, 0603"
R35: "RES, 309, 1%, 0.1 W, 0603"
R36: "RES, 1.21 k, 1%, 0.1 W, 0603"
R37: "RES, 5.36 k, 1%, 0.1 W, 0603"
R38: "RES, 4.64 k, 1%, 0.1 W, 0603"
R39: "RES, 1.96 k, 1%, 0.1 W, 0603"
S1 S2 S3 S4 S5 S6 S7 S8 S9 S10 S11 S12 S13 S14 S15 S16 S17 S18 S19 S20 S21 S22 S23 S24 S25 S26 S27 S28 S29 S30 S31 S32 S33 S34 S35 S36 S37 S38: "Switch, Tactile, SPST-NO, 0.05A, 12V, SMT"
U1: "450-mA High-Voltage Ultra-Low IQ Low-Dropout Regulator, PWP0020D"
U2: "Multiple Switch Detection Interface (MSDI) device, DCP0038A"
ZZ1: library part AssemblyNoteLabel
ZZ2 ZZ3 ZZ4: library part AssemblyNote

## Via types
v1: diameter 20, hole 10, Top Layer to Bottom Layer, tented both sides, 214 vias
v2: diameter 26, hole 7.87, Top Layer to Bottom Layer, tented both sides, 116 vias
v3: diameter 19.68, hole 7.87, Top Layer to Bottom Layer, tented both sides, 18 vias
v4: diameter 26, hole 7.87, Top Layer to Bottom Layer, 12 vias

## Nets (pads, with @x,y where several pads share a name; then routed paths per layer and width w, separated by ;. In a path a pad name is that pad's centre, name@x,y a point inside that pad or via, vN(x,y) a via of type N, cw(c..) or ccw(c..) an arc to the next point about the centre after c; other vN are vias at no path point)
CSI_IN4: R16.2 U2.27 | length 207.6
  Top Layer w10: U2.27@1616.14,870.63 1679.37,870.63 1682.08,867.92 1706.81,867.92 1735,839.72 1735,805 1750,790 R16.2@1770,790
CSI_IN5: R23.2 U2.29 | length 178.7
  Top Layer w10: U2.29@1616.14,910 1690,910 1750,850 R23.2@1770,850
CSI_IN6: R24.2 U2.30 | length 162
  Top Layer w10: U2.30@1616.14,929.69 1719.69,929.69 1739.37,910 R24.2@1770,910
CSI_IN7: R25.2 U2.31 | length 160.9
  Top Layer w10: U2.31@1616.14,949.37 1675.76,949.37 1692.7,966.31 R25.2@1770,966.31
CSI_IN8: R26.2 U2.32 | length 176
  Top Layer w10: U2.32@1616.14,969.06 1670.17,969.06 1723.73,1022.62 R26.2@1770,1022.62
CSI_IN9: R27.2 U2.33 | length 197.1
  Top Layer w10: U2.33@1616.14,988.74 1664.57,988.74 1735.75,1059.92 1735.75,1070 1744.67,1078.93 R27.2@1770,1078.93
CSO_IN10: R17.2 U2.34 | length 243.1
  Top Layer w10: U2.34@1616.14,1008.43 1658.98,1008.43 1717.87,1067.32 1717.87,1130 1723.11,1135.24 R17.2@1770,1135.24
CSO_IN11: R18.2 U2.35 | length 260.7
  Top Layer w10: U2.35@1616.14,1028.11 1653.39,1028.11 1700,1074.72 1700,1141.54 1750,1191.54 R18.2@1770,1191.54
CSO_IN12: R19.2 U2.36 | length 282.3
  Top Layer w10: U2.36@1616.14,1047.8 1647.8,1047.8 1680,1080 1680,1150 1770,1240 R19.2@1770,1247.85
CSO_IN13: R20.2 U2.1 | length 129
  Top Layer w10: U2.1@1383.86,1087.17 1394.41,1087.17 1420,1112.76 R20.2@1420,1195
CSO_IN14: R21.2 U2.2 | length 210.5
  Top Layer w10: U2.2@1383.86,1067.48 1457.48,1067.48 1480,1090 R21.2@1480,1195
CSO_IN15: R22.2 U2.3 | length 297.4
  Top Layer w10: U2.3@1383.86,1047.8 1507.8,1047.8 1571.23,1111.23 R22.2@1571.23,1195
CSO_IN16: C28.1 R28.2 R29.2 U2.4 | length 372.6
  Top Layer w10: R29.2@1240,1253.69 v2(1276.31,1253.69) 1276.31,1236.31 1282.62,1230 1305,1230 1325,1210 R28.2@1325,1195 1325,1110.83 1343.43,1092.4 1343.43,1040.02 1354.43,1029.02 1382.95,1029.02 U2.4@1383.86,1028.11
  Bottom Layer w10: C28.1@1240,1253.69 1270,1253.69 v2(1276.31,1253.69)
CSO_IN17: C30.1 R32.2 U2.5 | length 340
  Top Layer w10: R32.2@1240,1197.38 1257.62,1197.38 v2(1285,1170) 1300,1155 1300,1110.55 1325.55,1085 1325.55,1024.45 1341.57,1008.43 U2.5@1383.86,1008.43
  Bottom Layer w10: C30.1@1240,1197.38 1257.62,1197.38 v2(1285,1170)
CSO_IN18: C27.1 R30.2 R31.2 U2.6 | length 308
  Top Layer w10: R30.2@1240,1141.07 R31.2@1240,1084.76 v2(1282.91,1084.76) 1307.68,1060 1307.68,1017.05 1335.07,989.65 1382.95,989.65 U2.6@1383.86,988.74
  Bottom Layer w10: C27.1@1240,1084.76 v2(1282.91,1084.76)
CSO_IN19: C29.1 R33.2 U2.7 | length 216.1
  Top Layer w10: R33.2@1240,1028.46 1261.54,1028.46 v2(1280,1010) 1320.94,969.06 U2.7@1383.86,969.06
  Bottom Layer w10: C29.1@1240,1028.45 1261.54,1028.45 v2(1280,1010)
CSO_IN20: C31.1 R34.2 U2.8 | length 193.3
  Top Layer w10: R34.2@1240,972.15 v2(1280,972.15) 1287.85,972.15 1310.63,949.37 U2.8@1383.86,949.37
  Bottom Layer w10: C31.1@1240,972.15 v2(1280,972.15)
CSO_IN21: C32.1 R35.2 U2.10 | length 204.4
  Top Layer w10: R35.2@1240,915.24 1260,915.24 1274.76,930 v2(1280,930) 1310,930 1330,910 U2.10@1383.86,910
  Bottom Layer w10: C32.1@1240,915.24 1260,915.24 1274.76,930 v2(1280,930)
CSO_IN22: C33.1 R36.2 U2.11 | length 212.6
  Top Layer w10: R36.2@1241.95,858.93 1273.02,890 v2(1280,890) 1280.32,890.32 U2.11@1383.86,890.32
  Bottom Layer w10: C33.1@1241.95,858.93 1241.95,870.56 1261.39,890 v2(1280,890)
CSO_IN23: C34.1 R37.2 R38.2 R39.2 U2.12 | length 408.2
  Top Layer w10: R37.2@1240,687.38 1262.38,687.38 v2(1280,705) 1280,722.85 1262.87,739.98 1262.87,800 ; R38.2@1240,743.69 1259.16,743.69 ; R39.2@1240,800 1262.87,800 ; U2.12@1383.86,870.63 1300.63,870.63 1262.87,832.87 1262.87,800
  Bottom Layer w10: C34.1@1240,687.38 1262.38,687.38 v2(1280,705)
GND: C1.2 C2.2 C3.2 C4.2 C5.2 C6.2 C7.2 C8.2 C9.2 C10.2 C11.2 C12.2 C13.2 C14.2 C15.2 C16.2 C17.2 C18.2 C19.2 C20.2 C21.2 C22.2 C23.2 C24.2 C25.2 C26.2 C27.2 C28.2 C29.2 C30.2 C31.2 C32.2 C33.2 C34.2 D3.1 D4.1 D21.1 J1.1 J3.1 J7.1 J7.3 J7.5 J7.7 J8.2 J9.1 J10.4 Q2.2 R6.1 R7.1 R15.2 S37.3 S37.4 S38.3 S38.4 U1.7 U1.8 U1.9 U1.10 U1.11 U1.12 U1.13 U1.14 U1.21 U2.9 U2.28 U2.39 | length 3355.3
  Top Layer w10: v4(120,1700) 121.42,1701.42 S38.4@121.42,1810.87 S38.3@121.42,2169.13 v4(121.42,2257.45) S37.4@121.42,2345.76 S37.3@121.42,2704.03 121.42,2836.42 v2(125,2840) v2(125,2840) D21.1@125.04,2930 ; v2@1220,1482.54 v2(1220,1485) C4.2@1220,1530 ; v2(1280,1420) C1.2@1280,1456.45 ; v2(1335,505) 1340,510 C9.2@1340,560 ; U1.9@1383.54,1420.75 U1.10@1383.54,1395.16 1445.16,1395.16 1450,1400 ; U1.7@1383.54,1471.93 1428.07,1471.93 1430,1470 ; U2.9@1383.86,929.69 U2.39@1456.69,929.69 ; C13.2@1405.18,560 1405.18,474.82 v2(1410,470) ; v2(1460,470) 1460,520 1461.48,521.48 C14.2@1461.48,560 ; R7.1@1517.79,560 1517.79,522.21 1520,520 v2(1520,470) ; U2.39@1543.31,890.32 U2.28@1616.14,890.32 ; 1555,1400 1559.84,1395.16 U1.11@1615.83,1395.16 U1.12@1615.83,1420.75 ; 1570,1470 1571.93,1471.93 U1.14@1615.83,1471.93 ; C12.2@1574.1,560 1574.1,525.9 1580,520 v2(1580,470) ; v2(1730,1550) 1750,1530 ; C3.2@1750,1485.35 1750,1530 ; R6.1@1770,1420.31 1780.31,1420.31 1795,1435 v2(1814.37,1435) ; v2(1770,1550) 1750,1530 ; v4(2640,290) 2641.97,291.97 D3.1@2700,291.97 v4(2775,291.97) D4.1@2850,291.97
  Top Layer w15: J3.1@2400,1150 C2.2@2400,1293.7
  Bottom Layer w10: C32.2@1180,915.24 1181.95,913.29 C33.2@1181.95,858.93 ; v3(1456.69,888.35) v3(1500,888.35) ; v3(1456.69,931.66) v3(1500,931.66) ; v3(1500,845.04) v3(1500,888.35) ; v3(1500,974.96) v3(1500,931.66) ; v3(1543.31,888.35) v3(1500,888.35) ; v3(1543.31,931.66) v3(1500,931.66) ; 1735,745 1748.7,731.3 1769.69,731.3 C11.2@1770,730.99 ; 1735,1150 1735,1160.84 C17.2@1767.85,1193.69 ; C10.2@1770,674.68 C11.2@1770,730.99 ; C15.2@1770,790 C11.2@1770,730.99 ; C16.2@1770,1135.24 C17.2@1770,1191.54 C17.2@1767.85,1193.69 ; C18.2@1770,1247.85 1770,1195.84 C17.2@1767.85,1193.69 ; v3(1500,888.35) v3(1500,931.66)
  other v1: 208,116 358,116 508,116 658,116 808,116 958,116 1108,116 1258,116 1408,116 1558,116 1708,116 1858,116 2008,116 2158,116 2308,116 2458,116 2608,116 2758,116 133,266 433,266 733,266 883,266 1033,266 1183,266 1783,266 58,416 208,416 1408,416 1558,416 2608,416 2758,416 133,566 283,566 58,716 208,716 358,716 133,866 2683,866 58,1016 208,1016 2758,1016 133,1166 283,1166 433,1166 2233,1166 2533,1166 58,1316 208,1316 2458,1316 133,1466 733,1466 883,1466 1033,1466 1183,1466 2833,1466 58,1616 208,1616 508,1616 658,1616 808,1616 958,1616 1108,1616 1558,1616 433,1766 2533,1766 2833,1766 58,1916 208,1916 808,1916 2758,1916 133,2066 433,2066 583,2066 2533,2066 2683,2066 2833,2066 58,2216 208,2216 808,2216 2758,2216 433,2366 583,2366 883,2366 2533,2366 2683,2366 2833,2366 58,2516 208,2516 808,2516 958,2516 2758,2516 433,2666 583,2666 2533,2666 2683,2666 2833,2666 58,2816 358,2816 808,2816 958,2816 2758,2816 433,2966 2533,2966 2683,2966 2833,2966 658,3116 808,3116 2758,3116 133,3266 283,3266 433,3266 2533,3266 2683,3266 2833,3266 58,3416 208,3416 358,3416 508,3416 2758,3416 133,3566 283,3566 433,3566 2683,3566 2833,3566 58,3716 208,3716 358,3716 808,3716 1108,3716 1858,3716 2158,3716 2608,3716 2758,3716 133,3866 283,3866 433,3866 583,3866 1183,3866 1483,3866 1633,3866 2233,3866 2533,3866 2683,3866 2833,3866 58,4016 208,4016 358,4016 508,4016 808,4016 1108,4016 1258,4016 1558,4016 1858,4016 2158,4016 2608,4016 2758,4016 133,4166 283,4166 433,4166 1483,4166 2533,4166 2683,4166 2833,4166 58,4316 208,4316 358,4316 808,4316 958,4316 1108,4316 1858,4316 2008,4316 2158,4316 2608,4316 2758,4316 133,4466 283,4466 433,4466 1483,4466 2533,4466 2683,4466 2833,4466 58,4616 208,4616 358,4616 808,4616 1858,4616 2608,4616 2758,4616 133,4766 433,4766 583,4766 1183,4766 1333,4766 1483,4766 1633,4766 2233,4766 2383,4766 2533,4766 2683,4766 2833,4766 58,4916 658,4916 808,4916 958,4916 1108,4916 1708,4916 1858,4916 2008,4916 2158,4916 433,5066 1333,5066 1483,5066 2383,5066 2533,5066
  other v3: 1456.69,845.04 1543.31,845.04 1456.69,974.96 1543.31,974.96 1478.03,1467.01 1521.34,1467.01 1478.03,1510.31 1521.34,1510.31 1478.03,1553.62 1521.34,1553.62
LDO_EN: Q1.3 R6.2 U1.15 | length 1959.7
  Top Layer w10: U1.15@1615.83,1497.52 1662.48,1497.52 1690,1470 1690,1440 1709.69,1420.31 R6.2@1710,1420.31 ; v2(2045,1205) v2(2045,1485)
  Bottom Layer w10: Q1.3@1460,744.69 1519.69,744.69 1550,714.39 1725.61,714.39 1739.96,700.04 1739.96,655 1756.77,638.19 1950,638.19 1950,1110 v2(2045,1205) ; v2(1676.24,1483.76) 2043.76,1483.76 v2(2045,1485)
MISO: J2.3 U2.18 | length 1464.6
  Top Layer w10: v2(515,740) 555,700 830,700 v2(880,650) ; v2(1240,470) 1240,510 1304.13,574.13 1304.13,634.13 1340,670 1340,677.85 1341.62,679.48 1341.62,730.52 1340,732.15 1340,740 1352.52,752.52 U2.18@1383.86,752.52
  Bottom Layer w10: v2(515,740) 515,865 J2.3@600,950 ; v2(880,650) 1085,445 1215,445 v2(1240,470)
MOSI: J2.4 U2.17 | length 934.5
  Top Layer w10: J2.4@600,850 705,850 740,885 v2(1120,885) ; v2(1326.7,763.3) 1330,760 1342.21,772.21 U2.17@1383.86,772.21
  Bottom Layer w10: v2@1125,890 v2(1120,885) 1100,865 1100,810 1146.7,763.3 v2(1326.7,763.3)
MSDI_INT: D2.1 D5.2 J3.9 R13.1 | length 1092.6
  Top Layer w10: R13.1@1820,560 1790,560 1770,580 D5.2@1749.09,580 1749.09,420.91 1820,350 J3.9@2400,350 2450,350 2508.03,291.97 D2.1@2550,291.97
MSDI_RST: J3.10 R7.2 U2.21 | length 1332.6
  Top Layer w10: U2.21@1616.14,752.52 1582.52,752.52 1517.79,687.79 R7.2@1517.79,620 1517.79,602.21 1530,590 1600,590 1610,580 1610,420 1650,380 1750,380 1810,320 2330,320 J3.10@2400,250
NCS: J2.7 U2.15 | length 1261.9
  Top Layer w10: J2.7@600,550 1030,550 v2(1050,530) ; v2(1270,495.87) 1300.87,465 1355,465 1370.37,480.37 1370.37,630.91 1399.01,659.54 1419.54,659.54 1450,690 1450,780 1418.42,811.58 U2.15@1383.86,811.58
  Bottom Layer w10: v2(1050,530) 1115,465 1195,465 1225,495 1225,495.87 v2(1270,495.87)
NetC4_1: C4.1 U1.3 | length 172
  Top Layer w10: C4.1@1220,1590 1320,1590 1335.71,1574.29 U1.3@1383.54,1574.29
  Top Layer w15: U1.3@1382.18,1575.65 U1.3@1383.54,1574.29
NetC5_1: C5.1 J7.8 R8.1 | length 547.9
  Top Layer w10: R8.1@1180,627.38 1152.38,627.38 1125,600 v2(1125,595) 1125,506 J7.8@1350,281
  Bottom Layer w10: v2(1125,595) 1159.69,629.69 C5.1@1180,629.69
NetC7_1: C7.1 J7.6 R9.1 | length 511.8
  Top Layer w10: R9.1@1180,569.69 1180,530 v2(1180,500) 1180,480 1300,360 1371,360 J7.6@1450,281
  Bottom Layer w10: v2(1180,500) C7.1@1180,569.69
NetC10_1: C10.1 J7.4 R11.1 | length 716.7
  Top Layer w10: J7.4@1550,280 1620,350 v2(1730,350) ; v2(1800,420) 1880,500 v2(1880,675) R11.1@1830,674.99
  Bottom Layer w10: v2(1730,350) v2(1800,420) ; C10.1@1830,674.68 1859.69,674.68 ; 1859.69,674.68 1879.68,674.68 v2(1880,675) 1860.01,675 1859.69,674.68
NetC11_1: C11.1 J7.2 R14.1 | length 710.1
  Top Layer w10: J7.2@1650,280 1720,280 v2(1760,320) ; v2(1830,390) 1910,470 1910,700 v2(1880,730) ; R14.1@1830,731.3 v2@1880,731.3
  Bottom Layer w10: v2(1760,320) v2(1830,390) ; C11.1@1830.99,730 v2(1880,730)
NetC12_1: C12.1 U2.20 | length 130.2
  Top Layer w10: C12.1@1574.1,620 1574.1,651.82 1616.14,693.86 U2.20@1616.14,732.84
NetC13_1: C13.1 U2.23 | length 300.1
  Top Layer w10: C13.1@1405.18,620 1405.28,620 1467.87,682.6 1467.87,682.7 1474.72,689.55 1474.72,720 1544.8,790.08 1545.26,790.08 1547.07,791.89 U2.23@1616.14,791.89
NetC14_1: C14.1 U2.22 | length 253.7
  Top Layer w10: C14.1@1461.48,620 1461.48,624.31 1498.54,661.37 1498.54,718.54 1552.21,772.21 U2.22@1616.14,772.21
NetC16_1: C16.1 R17.1 S1.1 S1.2 S7.1 S7.2 S13.1 S13.2 S19.1 S19.2 S25.1 S25.2 S31.1 S31.2 | length 5370.6
  Top Layer w10: v4(710,1676.72) 712.46,1676.72 727.87,1692.13 1897.87,1692.13 1967.87,1622.13 1967.87,1207.87 1895.24,1135.24 v2(1890,1135.24) R17.1@1830,1135.24 ; v2(713.58,1823.58) S31.2@713.58,1910.87 S31.1@713.58,2269.13 S25.2@713.58,2470.87 S25.1@713.58,2829.13 S19.2@713.58,2967.2 S19.1@713.58,3325.47 v2(765.47,3325.47) ; S1.1@713.58,5009.13 S1.2@713.58,4650.87 S7.1@713.58,4479.13 S7.2@713.58,4120.87 S13.1@713.58,3941.02 S13.2@713.58,3582.76 v2(767.24,3582.76)
  Bottom Layer w10: v4(710,1676.72) v2@710,1820 ; v2(765.47,3325.47) 767.24,3327.24 v2(767.24,3582.76) ; C16.1@1830,1135.24 v2(1890,1135.24)
NetC17_1: C17.1 R18.1 S2.1 S2.2 S8.1 S8.2 S14.1 S14.2 S20.1 S20.2 S26.1 S26.2 S32.1 S32.2 | length 4958.4
  Top Layer w10: v2(1060,1660) 1074.25,1674.25 1890,1674.25 1949.53,1614.72 1950,1614.72 1950,1233.09 1908.46,1191.54 v2(1890,1191.54) R18.1@1830,1191.54 ; v2(1060,1830) 1060,1907.28 S32.2@1063.58,1910.87 S32.1@1063.58,2269.13 S26.2@1063.58,2470.87 S26.1@1063.58,2829.13 S20.2@1063.58,2970.87 S20.1@1063.58,3329.13 v2(1119.13,3329.13) ; S2.1@1063.58,5009.13 S2.2@1063.58,4650.87 S8.1@1063.58,4479.13 S8.2@1063.58,4120.87 S14.1@1063.58,3942.8 S14.2@1063.58,3584.53 v2(1114.53,3584.53)
  Bottom Layer w10: v2(1060,1660) v2(1060,1830) ; v2(1114.53,3584.53) 1119.13,3579.93 v2(1119.13,3329.13) ; C17.1@1830,1191.54 v2(1890,1191.54)
NetC18_1: C18.1 R19.1 S3.1 S3.2 S9.1 S9.2 S15.1 S15.2 S21.1 S21.2 S27.1 S27.2 S33.1 S33.2 | length 4490
  Top Layer w10: S3.1@1413.58,5009.13 S3.2@1413.58,4650.87 S9.1@1413.58,4479.13 S9.2@1413.58,4120.87 S15.1@1413.58,3942.8 S15.2@1413.58,3584.53 v2(1475.47,3584.53) ; v2(1460,1644.17) 1472.21,1656.38 1882.6,1656.38 1930,1608.97 1930,1300 v2(1880,1250) 1877.85,1247.85 R19.1@1830,1247.85 ; v2(1460,1820) 1413.58,1866.42 S33.2@1413.58,1910.87 S33.1@1413.58,2269.13 S27.2@1413.58,2470.87 S27.1@1413.58,2829.13 S21.2@1413.58,2970.87 S21.1@1413.58,3329.13 1479.13,3329.13 v2(1480,3330)
  Bottom Layer w10: v2(1460,1644.17) v2(1460,1820) ; v2(1475.47,3584.53) 1480,3580 v2(1480,3330) ; C18.1@1830,1247.85 1877.85,1247.85 v2(1880,1250)
NetC19_1: C19.1 R20.1 S4.1 S4.2 S10.1 S10.2 S16.1 S16.2 S22.1 S22.2 S28.1 S28.2 S34.1 S34.2 | length 4564.8
  Top Layer w10: R20.1@1420,1255 1420,1350 v2(1405,1365) 1468.41,1365 1469.28,1365.87 1490.72,1365.87 1491.59,1365 1835,1365 1890,1420 1890,1530 1842.5,1577.5 v2(1830,1577.5) ; S4.1@1763.58,5009.13 S4.2@1763.58,4650.87 S10.1@1763.58,4479.13 S10.2@1763.58,4120.87 S16.1@1763.58,3942.8 S16.2@1763.58,3584.53 v2(1834.53,3584.53) ; v2(1830,1830) 1830,1890 1809.13,1910.87 S34.2@1763.58,1910.87 S34.1@1763.58,2269.13 S28.2@1763.58,2470.87 S28.1@1763.58,2829.13 S22.2@1763.58,2970.87 S22.1@1763.58,3329.13 v2(1839.13,3329.13)
  Bottom Layer w10: v2(1405,1365) 1420,1350 C19.1@1420,1255 ; v2(1830,1577.5) v2(1830,1830) ; v2(1834.53,3584.53) 1834.53,3333.74 v2(1839.13,3329.13)
NetC20_1: C20.1 R21.1 S5.1 S5.2 S11.1 S11.2 S17.1 S17.2 S23.1 S23.2 S29.1 S29.2 S35.1 S35.2 | length 4704.1
  Top Layer w10: R21.1@1480,1255 v2(1480,1340) 1850,1340 v2(1890,1380) ; S5.1@2113.58,5009.13 S5.2@2113.58,4650.87 S11.1@2113.58,4479.13 S11.2@2113.58,4120.87 S17.1@2113.58,3942.8 S17.2@2113.58,3584.53 v2(2165.47,3584.53) ; v2(2165.47,3335.47) 2159.13,3329.13 S23.1@2113.58,3329.13 S23.2@2113.58,2970.87 S29.1@2113.58,2829.13 S29.2@2113.58,2470.87 S35.1@2113.58,2269.13 S35.2@2113.58,1910.87 2169.13,1910.87 2200,1880 v2(2200,1840) ; v2(2200,1380) v2(2200,1670)
  Bottom Layer w10: C20.1@1480,1255 1480,1310 v2(1480,1340) ; v2(1890,1380) v2(2200,1380) ; v2(2165.47,3335.47) v2(2165.47,3584.53) ; v2(2200,1670) v2(2200,1840)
